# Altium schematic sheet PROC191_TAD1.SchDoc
size 431 x 279 mm; Date: Not shown in title block; ApprovedBy: Not shown in title block; CheckedBy: Not shown in title block; Author: Not shown in title block; CompanyName: Not shown in title block; Engineer: Not shown in title block; Organization: Not shown in title block; Address1: Not shown in title block; Address2: Not shown in title block; Address3: Not shown in title block; Address4: Not shown in title block; DocumentNumber: 4; Revision: Use project parameter SCH_Rev; SheetNumber: 7; SheetTotal: 8; PageSetup: Record=PageOptions¦CenterHorizontal=True¦CenterVertical=True¦PrintScale=1.00¦XCorrection=1.00¦YCorrection=1.00¦PrintKind=0¦BorderSize=5000000¦LeftOffset=0¦BottomOffset=0¦Orientation=2¦PaperLength=1000¦PaperWidth=1000¦Scale=100¦PaperSource=15¦PrintQuality=600¦MediaType=1¦DitherType=10¦PaperKind=Letter¦PrintScaleMode=1
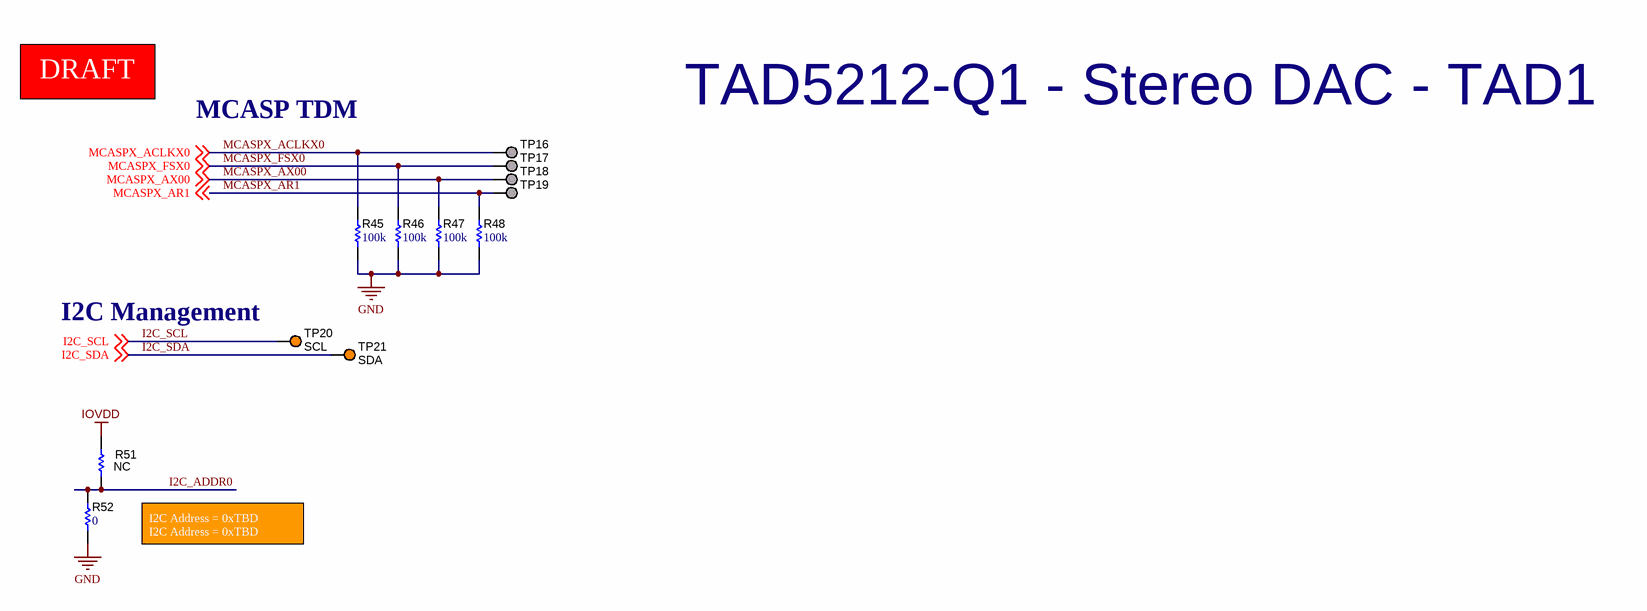
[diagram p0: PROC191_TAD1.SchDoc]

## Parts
R45  ValueDisplayed: 100k  [0402]  (hidden comment: RMCF0402FT100K)
R46  ValueDisplayed: 100k  [0402]  (hidden comment: RMCF0402FT100K)
R47  ValueDisplayed: 100k  [0402]  (hidden comment: RMCF0402FT100K)
R48  ValueDisplayed: 100k  [0402]  (hidden comment: RMCF0402FT100K)
R51  NC  [0603]  (no BOM)
R52  ValueDisplayed: 0  [0603]  (hidden comment: RMCF0603ZT0R00)
TP16  AVDD  [TP_SM_1MM]  (value not drawn)  (no BOM)
TP17  AVDD  [TP_SM_1MM]  (value not drawn)  (no BOM)
TP18  AVDD  [TP_SM_1MM]  (value not drawn)  (no BOM)
TP19  AVDD  [TP_SM_1MM]  (value not drawn)  (no BOM)
TP20  SCL  [Keystone5003]
TP21  SDA  [Keystone5003]

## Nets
GND: R45.1 R46.1 R47.1 R48.1 R52.1
IOVDD: R51.2
I2C_ADDR0: R51.1 R52.2
I2C_SCL: TP20.1 ; off-sheet I2C_SCL
I2C_SDA: TP21.1 ; off-sheet I2C_SDA
MCASPX_ACLKX0: R45.2 TP16.1 ; off-sheet MCASPX_ACLKX0
MCASPX_AR1: R48.2 TP19.1 ; off-sheet MCASPX_AR1
MCASPX_AX00: R47.2 TP18.1 ; off-sheet MCASPX_AX00
MCASPX_FSX0: R46.2 TP17.1 ; off-sheet MCASPX_FSX0

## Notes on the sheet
- DRAFT
- TAD5212-Q1 - Stereo DAC - TAD1
- MCASP TDM
- (near TP20) I2C Management
- I2C Address = 0xTBD
  I2C Address = 0xTBD

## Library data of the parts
R45-R48 = CMP-0026753-1: RES, 100 k, 1%, 0.063 W, AEC-Q200 Grade 0, 0402; Manufacturer: Stackpole Electronics Inc; Power_W: 63mW; TempCo: 100 ppm/C; U/M: EA; Value: 100k; EIA_Code: E96; SizeX_mm: 1; SizeY_mm: 0.5; SizeZ_mm: 0.6; Value2: 0.063W; AEC Qualified: Y; VDC_V: 50V; AEC Grade: 0; AEC Category: Q200
R51 = CMP-0023343-3: RES, 0, 1%, 0.1 W, AEC-Q200 Grade 0, 0603; Manufacturer: Stackpole Electronics Inc; PartNumber: RMCF0603ZT0R00; Power_W: 100mW; TempCo: ppm/C; Value_Code: 0; U/M: EA; Value: 0; SizeX_mm: 1.6; SizeY_mm: 0.8; SizeZ_mm: 1; Value2: 0.1W; SizeArea_mm2: 1.28; AEC Qualified: Y; AEC Category: Q200
R52 = CMP-0023343-3: RES, 0, 1%, 0.1 W, AEC-Q200 Grade 0, 0603; Manufacturer: Stackpole Electronics Inc; Power_W: 100mW; TempCo: ppm/C; U/M: EA; Value: 0; SizeX_mm: 1.6; SizeY_mm: 0.8; SizeZ_mm: 1; Value2: 0.1W; SizeArea_mm2: 1.28; AEC Qualified: Y; AEC Category: Q200
TP16-TP19 = CMP-0003825-1: 1mm Test Point, SMT; Manufacturer: Any
TP20 TP21 = CMP-0055140-1: Test Point, Miniature, Orange, TH; Manufacturer: Keystone; ContactFinish: Silver; CNHeader: FALSE; CT: TRUE; Green_Lifecycle: Active; Green_REACh: Passed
